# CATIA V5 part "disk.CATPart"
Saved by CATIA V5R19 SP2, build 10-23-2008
Part number: disk
Bounding box of the stored display mesh (mm): x 1163.466 to 1641.845, y 626 to 748, z 61.014 to 447.359
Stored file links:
  C:\BEHROOZ\catia learning\tarh haye mashin\hb\disk.CATPart
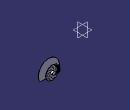
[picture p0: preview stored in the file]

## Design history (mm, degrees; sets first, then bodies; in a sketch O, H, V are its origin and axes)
Body1 (main body)
  Plane1: stored without definition
  DatumCurve1
  Plane2: stored without definition
  Sketch1 on Plane1, origin (0, 756, 0), H (-1, 0, 0), V (0, 0, 1)
    circle A1 centre (-1402.6545, 208.175) radius 147.1706
    circle A2 centre (-1454.7163, 331.4554) radius 4.4914
    circle A3 centre (-1425.8065, 331.0642) radius 4.4914
    circle A4 centre (-1399.7706, 318.4919) radius 4.4914
    circle A5 centre (-1381.4874, 296.0942) radius 4.4914
    circle A6 centre (-1374.3828, 268.0682) radius 4.4914
    circle A7 centre (-1352.2953, 332.1606) radius 4.4914
    circle A8 centre (-1332.1296, 311.4417) radius 4.4914
    circle A9 centre (-1322.6094, 284.1415) radius 4.4914
    circle A10 centre (-1325.5188, 255.3758) radius 4.4914
    circle A11 centre (-1340.3125, 230.5347) radius 4.4914
    circle A12 centre (-1279.3741, 260.2367) radius 4.4914
    circle A13 centre (-1279.7653, 231.3269) radius 4.4914
    circle A14 centre (-1292.3376, 205.291) radius 4.4914
    circle A15 centre (-1314.7353, 187.0078) radius 4.4914
    circle A16 centre (-1342.7613, 179.9032) radius 4.4914
    circle A17 centre (-1278.6689, 157.8157) radius 4.4914
    circle A18 centre (-1299.3878, 137.65) radius 4.4914
    circle A19 centre (-1326.688, 128.1299) radius 4.4914
    circle A20 centre (-1355.4537, 131.0392) radius 4.4914
    circle A21 centre (-1380.2948, 145.8329) radius 4.4914
    circle A22 centre (-1350.5928, 84.8945) radius 4.4914
    circle A23 centre (-1379.5026, 85.2857) radius 4.4914
    circle A24 centre (-1405.5385, 97.858) radius 4.4914
    circle A25 centre (-1423.8217, 120.2557) radius 4.4914
    circle A26 centre (-1430.9263, 148.2817) radius 4.4914
    circle A27 centre (-1453.0138, 84.1893) radius 4.4914
    circle A28 centre (-1473.1795, 104.9082) radius 4.4914
    circle A29 centre (-1482.6996, 132.2084) radius 4.4914
    circle A30 centre (-1479.7903, 160.9741) radius 4.4914
    circle A31 centre (-1464.9966, 185.8152) radius 4.4914
    circle A32 centre (-1525.935, 156.1132) radius 4.4914
    circle A33 centre (-1525.5438, 185.023) radius 4.4914
    circle A34 centre (-1512.9715, 211.0589) radius 4.4914
    circle A35 centre (-1490.5738, 229.3421) radius 4.4914
    circle A36 centre (-1462.5478, 236.4467) radius 4.4914
    circle A37 centre (-1526.6402, 258.5342) radius 4.4914
    circle A38 centre (-1505.9213, 278.6999) radius 4.4914
    circle A39 centre (-1478.6211, 288.2201) radius 4.4914
    circle A40 centre (-1449.8554, 285.3107) radius 4.4914
    circle A41 centre (-1425.0143, 270.517) radius 4.4914
  Pad1: profile Sketch1, direction (0, 1, 0), length -48, opposite side length 54
  Sketch2 on Plane2, origin (0, 756, 0), H (-1, 0, 0), V (0, 0, 1)
    circle A1 centre (-1402.6545, 208.175) radius 40.6715
  Pad2: profile Sketch2, direction (0, 1, 0), length -48, opposite side length 8
Body2
  Sketch3 on end face of Pad1, origin (0, 708, 0), H (-1, 0, 0), V (0, 0, 1)
    arc A1 centre (-1418.3403, 217.9258) radius 122.3072 from (-1318.161, 288.0911) to (-1305.4782, 170.7961) cw
    line L1 (-1301.6546, 158.6604) -> (-1286.7701, 149.2293)
    arc A2 centre (-1386.9053, 214.3657) radius 144.4347 from (-1253.0823, 160.0263) to (-1277.8584, 309.0766) ccw
    line L2 (-1306.8209, 312.3204) -> (-1315.1714, 306.199)
    arc A3 centre (-1294.1014, 294.969) radius 21.5141 from (-1277.8584, 309.0766) to (-1306.8209, 312.3204) ccw
    arc A4 centre (-1274.4353, 168.6968) radius 23.0462 from (-1253.0823, 160.0263) to (-1286.7701, 149.2293) cw
    arc A5 centre (-1307.4148, 295.6177) radius 13.1199 from (-1318.161, 288.0911) to (-1315.1714, 306.199) cw
    arc A6 centre (-1296.3741, 166.9943) radius 9.866 from (-1305.4782, 170.7961) to (-1301.6546, 158.6604) ccw
  Pad3: profile Sketch3, direction (0, 1, 0), length -32, opposite side length -18
  Sketch4 on start face of Pad3, origin (0, 726, 0), H (-1, 0, 0), V (0, 0, 1)
    arc A1 centre (-1386.4264, 211.3663) radius 135.2498 from (-1300.2316, 315.5917) to (-1267.6534, 146.671) cw
  Pocket1: profile Sketch4, direction (0, -1, 0), length 15, opposite side length -30
  Fillet1: radius 11, on start face of Pad3
  Sketch5 on start face of Pad3, origin (0, 726, 0), H (-1, 0, 0), V (0, 0, 1)
    circle A1 centre (-1275.3352, 256.2442) radius 10.4378
    circle A2 centre (-1288.5378, 285.1892) radius 10.4378
    circle A3 centre (-1270.0032, 223.9984) radius 10.4378
    circle A4 centre (-1275.3352, 183.8817) radius 10.4378
    line L1 (-1280.8827, 158.5212) -> (-1288.8026, 163.5393)
    arc A5 centre (-1418.3399, 217.9258) radius 133.3069 from (-1292.4627, 174.0434) to (-1309.1511, 294.4015) ccw
    arc A6 centre (-1307.4148, 295.6177) radius 2.1198 from (-1308.6681, 297.3273) to (-1309.1511, 294.4015) ccw
    line L2 (-1308.6681, 297.3273) -> (-1300.3175, 303.4488)
    arc A7 centre (-1294.1013, 294.9691) radius 10.514 from (-1286.1633, 301.8635) to (-1300.3175, 303.4488) ccw
    arc A8 centre (-1386.9048, 214.3658) radius 133.4342 from (-1263.2741, 164.1647) to (-1286.1633, 301.8635) ccw
    arc A9 centre (-1274.4352, 168.6966) radius 12.0461 from (-1280.8827, 158.5212) to (-1263.2741, 164.1647) ccw
    arc A10 centre (-1284.0134, 171.0979) radius 8.9481 from (-1292.4627, 174.0434) to (-1288.8026, 163.5393) ccw
  Pocket2: profile Sketch5, direction (0, -1, 0), length 6
  Fillet2: radius 4, on edge [face of Fillet1 | face of Pocket2 from Sketch5.A8]
  Fillet3: radius 2, on end face of Pocket2
  Fillet4: radius 2, on start face of Pad3 (x4)
Body3
  Plane3: stored without definition
  DatumCurve2
  Sketch6 on Plane3, origin (0, 756, 0), H (-1, 0, 0), V (0, 0, 1)
    projected circle E1 centre (-1402.6545, 208.175) radius 239.1923 from edge of DatumCurve2
    projected arc E2 centre (-1402.6545, 208.175) radius 239.1923 from (-1211.2152, 64.7736) to (-1517.3294, 418.086) ccw from edge of DatumCurve2
    projected arc E3 centre (-1402.6545, 208.175) radius 239.1923 from (-1517.3294, 418.086) to (-1606.5485, 83.1141) ccw from edge of DatumCurve2
    line L1 (-1211.2152, 64.7736) -> (-1606.5485, 83.1141)
    point P1 (-1517.3294, 418.086)
    point P4 (-1517.3294, 418.086)
    coincidence: P1 P4
  Pad4: profile Sketch6, direction (0, 1, 0), length -130, opposite side length 128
